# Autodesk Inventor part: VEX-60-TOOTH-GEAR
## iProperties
Created: 2007-08
Part Number: VEX-60-TOOTH-GEAR
Material: ABS Plastic
Document SubType Name: Modeling
Density: 1.06 g/cm^3
Mass: 9.01025 g
Surface Area: 99.3042 cm^2
Volume: 8.50023 cm^3
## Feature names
1. Base1
